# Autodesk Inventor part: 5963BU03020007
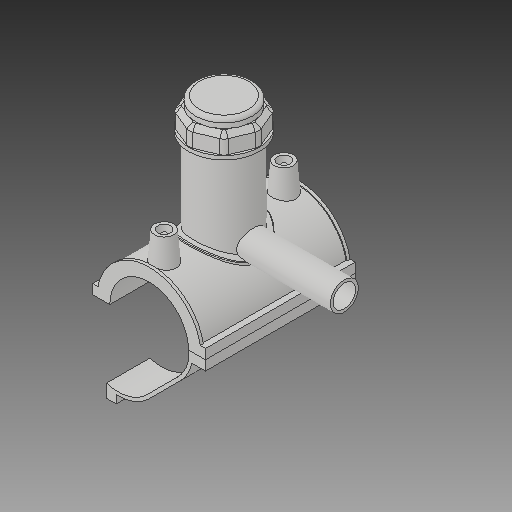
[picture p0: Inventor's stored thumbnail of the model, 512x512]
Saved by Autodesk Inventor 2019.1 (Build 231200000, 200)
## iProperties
Created: 2017-07
Part Number: 5963BU03020007
Material: Generic
Description: PLASSON TAPPING SADDLE 2''IPS x 1 3/4''CTS
Document SubType Name: Modeling
Designer: KIM
Mass: 1712.7 g
Surface Area: 2671.49 cm^2
Volume: 1712.7 cm^3
Density: 1 g/cm^3
Appearance: Default
Author: KIM
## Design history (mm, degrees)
derived "5963B.ipt"
feature "Solid1::5963B.ipt"
feature "Solid2::5963B.ipt"
feature "Solid4::5963B.ipt"
feature "Solid5::5963B.ipt"
tag "TaggingFeature1"
body "Solid1"
body "Solid2"
other parameters: "d0" = 62.1, "d2" = 88.9, "d3" = 15.525, "d4" = 118.11, "d5" = 0, "d6" = 0.1, "d8" = 0, "d19" = 6, "d20" = 6, "d21" = 70.866, "d23" = 0, "d24" = 35.433, "d26" = 0, "d29" = 3, "d30" = 20.7, "d31" = 6, "d32" = 0, "d33" = 0, "d34" = 0.6, "d40" = 41.9796, "d41" = 55.89, "d43" = 0, "d45" = 0, "d47" = 111.231, "d70" = 15, "d72" = 0, "d73" = 6, "d75" = 5, "d76" = 0, "d77" = 3.105, "d78" = 61.05, "d79" = 15, "d80" = 47.244, "d82" = 5 deg, "d84" = 4, "d85" = 14, "d86" = 0, "d87" = 3, "d88" = 0, "d89" = 1, "d90" = 1, "d91" = 94.488, "d92" = 0, "d93" = 0.5, "d94" = 32.68421, "d96" = 82.3446, "d97" = 2.3622, "d98" = 0, "d102" = 0.621, "d120" = 140 deg, "d121" = 24.228, "d122" = 20 deg, "d123" = 161.46, "d124" = 48.438, "d126" = 0, "d143" = 63.963, "d145" = 14.33077, "d149" = 0.9315, "d150" = 15.76385, "d153" = 118.11, "d154" = 0, "d156" = 40.365, "d157" = 160 deg, "d159" = 3.726, "d161" = 0.9315, "d162" = 70.866, "d163" = 0, "d164" = 31.05, "d167" = 6.21, "d168" = 39.38049, "d170" = 3.2805, "d172" = 0, "d173" = 1, "d175" = 31.05, "d176" = 20 deg, "d177" = 4.347, "d178" = 18.63, "d180" = 0, "d183" = 7.452, "d184" = 3.4776, "d185" = 38.38575, "d186" = 38.38575, "d187" = 40.365, "d188" = 5.589, "d189" = 4.347, "d190" = 0, "d191" = 60.5475, "d193" = 6.1236, "d194" = 4.13385, "d195" = 90 deg, "d197" = 0, "d199" = 0, "d200" = 9.315, "d202" = 0, "d203" = 98.044, "d204" = 53.0955, "d205" = 39.123, "d206" = 47.5065, "d207" = 73.533, "d208" = 76.47432, "d209" = 91.18092, "d210" = 48.0654, "d211" = 55.89, "d212" = 44.712, "d213" = -2.4012, "d216" = 0, "d217" = 6.21, "d218" = 3.105, "d219" = 0.621, "d222" = 62.1, "d224" = 0, "d230" = 3.726, "d233" = 6, "d236" = 44.45, "d237" = 35.433, "d238" = 6.02433, "d240" = 35.433, "d241" = 35.433, "d242" = 35.433, "d243" = 6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
